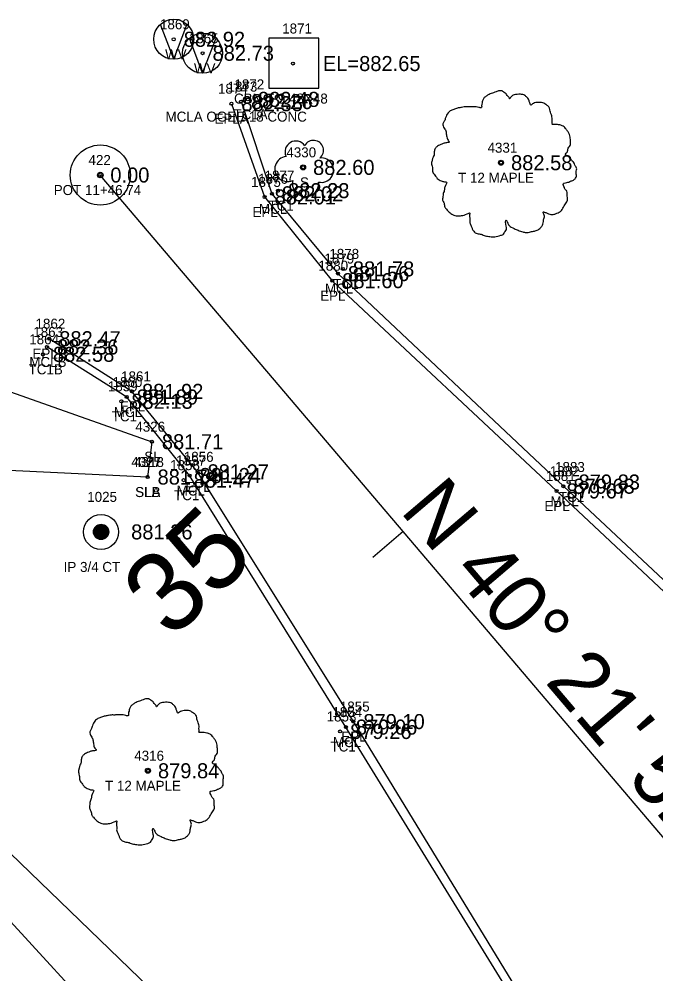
# Model space of a CAD drawing. Extents: x 1622501 to 1626664, y 1117816 to 1121579.
# Drawn here: x 1625349.1 to 1625412.8, y 1120671 to 1120766.3 of the extents above; entities that cross this region are included whole.
import ezdxf

# ---------------------------------------------------------------- set-up
doc = ezdxf.new("R2010")
doc.units = 0
for name, color, linetype in [('RD_EX_Bldg', 7, 'Continuous'), ('RD_EX_Conc', 7, 'Continuous'), ('RD_EX_Conc_txCode', 7, 'Continuous'), ('RD_EX_DR_Inlet', 7, 'Continuous'), ('RD_EX_DR_Inlet_txCode', 7, 'Continuous'), ('RD_EX_DV_Prop_txCode', 7, 'Continuous'), ('RD_EX_DV_PropPin', 7, 'Continuous'), ('RD_EX_Road', 7, 'Continuous'), ('RD_EX_Road_txCode', 7, 'Continuous'), ('RD_EX_TX_Conc_ELEV', 7, 'Continuous'), ('RD_EX_TX_DR_Inlet_ELEV', 7, 'Continuous'), ('RD_EX_TX_DV_Prop_ELEV', 7, 'Continuous'), ('RD_EX_TX_Road_ELEV', 7, 'Continuous'), ('RD_EX_TX_UT_ELEV', 7, 'Continuous'), ('RD_EX_TX_VEG_ELEV', 7, 'Continuous'), ('RD_EX_UT', 7, 'Continuous'), ('RD_EX_UT_txCode', 7, 'Continuous'), ('RD_EX_VEG', 7, 'Continuous'), ('RD_EX_VEG_txCode', 7, 'Continuous'), ('RD_HC_Cl', 7, 'Continuous'), ('RD_HC_Data', 7, 'Continuous'), ('RD_HC_Data_Tic', 7, 'Continuous'), ('RD_HC_Survey_ELEV', 7, 'Continuous'), ('RD_HC_TX_Sta50', 7, 'Continuous'), ('RD_HC_txCode', 7, 'Continuous'), ('RD_SMD_Locator', 7, 'Continuous')]:
    doc.layers.add(name, color=color, linetype=linetype)

msp = doc.modelspace()

# ---------------------------------------------------------------- linework, layer by layer
at = {"layer": 'RD_EX_Bldg'}
msp.add_lwpolyline([(1625324.146, 1120631.464), (1625359.464, 1120663.962), (1625332.745, 1120693.129), (1625297.427, 1120660.63), (1625324.146, 1120631.464)], dxfattribs=at)
at = {"layer": 'RD_EX_Conc'}
for points in [[(1625371.324, 1120758.09), (1625374.405, 1120748.878), (1625381, 1120740.913), (1625403.527, 1120719.673), (1625432.461, 1120692.614), (1625438.681, 1120687.207)], [(1625399.274, 1120667.189), (1625381.796, 1120695.608), (1625366.181, 1120720.74), (1625359.897, 1120728.578), (1625351.935, 1120733.581)]]:
    msp.add_lwpolyline(points, dxfattribs=at)
at = {"layer": 'RD_EX_DR_Inlet'}
msp.add_line((1625379.091, 1120759.438), (1625379.091, 1120764.438), dxfattribs=at)
msp.add_lwpolyline([(1625379.091, 1120759.438), (1625379.091, 1120764.438), (1625374.091, 1120764.438), (1625374.091, 1120759.438)], close=True, dxfattribs=at)
at = {"layer": 'RD_EX_DV_PropPin'}
for p, q in [((1625356.608, 1120714.912), (1625356.608, 1120715.304)), ((1625356.643, 1120714.81), (1625356.643, 1120715.406)), ((1625356.678, 1120714.739), (1625356.678, 1120715.478)), ((1625356.713, 1120714.682), (1625356.713, 1120715.535)), ((1625356.748, 1120714.634), (1625356.748, 1120715.582)), ((1625356.783, 1120714.593), (1625356.783, 1120715.623)), ((1625356.818, 1120714.557), (1625356.818, 1120715.659)), ((1625356.853, 1120714.526), (1625356.853, 1120715.69)), ((1625356.888, 1120714.498), (1625356.888, 1120715.718)), ((1625356.923, 1120714.474), (1625356.923, 1120715.743)), ((1625356.958, 1120714.452), (1625356.958, 1120715.764)), ((1625356.993, 1120714.432), (1625356.993, 1120715.784)), ((1625357.028, 1120714.415), (1625357.028, 1120715.801)), ((1625357.063, 1120714.401), (1625357.063, 1120715.816)), ((1625357.098, 1120714.388), (1625357.098, 1120715.829)), ((1625357.133, 1120714.377), (1625357.133, 1120715.84)), ((1625357.168, 1120714.367), (1625357.168, 1120715.849)), ((1625357.203, 1120714.36), (1625357.203, 1120715.856)), ((1625357.238, 1120714.354), (1625357.238, 1120715.862)), ((1625357.273, 1120714.35), (1625357.273, 1120715.866)), ((1625357.308, 1120714.348), (1625357.308, 1120715.868)), ((1625357.343, 1120714.347), (1625357.343, 1120715.869)), ((1625357.378, 1120714.348), (1625357.378, 1120715.868)), ((1625357.413, 1120714.35), (1625357.413, 1120715.866)), ((1625357.448, 1120714.354), (1625357.448, 1120715.862)), ((1625357.483, 1120714.36), (1625357.483, 1120715.856)), ((1625357.518, 1120714.367), (1625357.518, 1120715.849)), ((1625357.553, 1120714.377), (1625357.553, 1120715.84)), ((1625357.588, 1120714.388), (1625357.588, 1120715.829)), ((1625357.623, 1120714.401), (1625357.623, 1120715.816)), ((1625357.658, 1120714.415), (1625357.658, 1120715.801)), ((1625357.693, 1120714.432), (1625357.693, 1120715.784)), ((1625357.728, 1120714.452), (1625357.728, 1120715.764)), ((1625357.763, 1120714.474), (1625357.763, 1120715.743)), ((1625357.798, 1120714.498), (1625357.798, 1120715.718)), ((1625357.833, 1120714.526), (1625357.833, 1120715.69)), ((1625357.868, 1120714.557), (1625357.868, 1120715.659)), ((1625357.904, 1120714.593), (1625357.904, 1120715.623)), ((1625357.939, 1120714.634), (1625357.939, 1120715.582)), ((1625357.974, 1120714.682), (1625357.974, 1120715.535)), ((1625358.009, 1120714.739), (1625358.009, 1120715.478)), ((1625358.044, 1120714.81), (1625358.044, 1120715.406)), ((1625358.079, 1120714.912), (1625358.079, 1120715.304))]:
    msp.add_line(p, q, dxfattribs=at)
for radius in [1.75, 0.761]:
    msp.add_circle((1625357.343, 1120715.108), radius, dxfattribs=at)
at = {"layer": 'RD_EX_Road'}
for points in [[(1625370.364, 1120757.883), (1625373.672, 1120748.564), (1625380.435, 1120740.201), (1625402.846, 1120719.199), (1625431.886, 1120691.989), (1625438.078, 1120686.6), (1625445.87, 1120680.321), (1625455.5, 1120677.046), (1625462.434, 1120676.301), (1625468.216, 1120676.722), (1625470.162, 1120677.112), (1625477.587, 1120679.763), (1625479.605, 1120680.725), (1625482.392, 1120682.638), (1625486.867, 1120686.354)], [(1625193.609, 1120405.268), (1625230.886, 1120440.454), (1625264.542, 1120472.475), (1625302.319, 1120508.619), (1625336.712, 1120541.707), (1625372.736, 1120576.316), (1625405.889, 1120608.621), (1625410.004, 1120614.055), (1625413.225, 1120619.884), (1625415.316, 1120626.889), (1625415.744, 1120636.202), (1625413.752, 1120644.595), (1625411.823, 1120648.585), (1625399.983, 1120667.632), (1625382.545, 1120696.163), (1625366.978, 1120721.108), (1625360.429, 1120729.145), (1625352.16, 1120734.407)]]:
    msp.add_lwpolyline(points, dxfattribs=at)
at = {"layer": 'RD_EX_UT'}
for p, q in [((1625364.595, 1120762.324), (1625363.291, 1120765.806)), ((1625364.595, 1120762.324), (1625365.917, 1120765.769)), ((1625367.476, 1120760.927), (1625366.172, 1120764.41)), ((1625367.476, 1120760.927), (1625368.798, 1120764.373))]:
    msp.add_line(p, q, dxfattribs=at)
for centre in [(1625364.595, 1120764.316), (1625367.476, 1120762.92)]:
    msp.add_circle(centre, 2, dxfattribs=at)
at = {"layer": 'RD_EX_VEG'}
for points in [[(1625361.983, 1120720.589), (1625323.865, 1120722.423), (1625334.599, 1120733.918), (1625362.415, 1120724.119), (1625361.983, 1120720.589)], [(1625324.296, 1120690.104), (1625333.335, 1120697.407), (1625365.129, 1120666.703), (1625351.745, 1120650.415)]]:
    msp.add_lwpolyline(points, dxfattribs=at)
for centre, radius in [((1625397.3, 1120751.985), 0.25), ((1625377.522, 1120751.52), 0.25), ((1625397.287, 1120751.966), 0.0001), ((1625362.023, 1120691.25), 0.25), ((1625362.01, 1120691.231), 0.0001)]:
    msp.add_circle(centre, radius, dxfattribs=at)
for centre, radius, start, end in [((1625376.801, 1120753.067), 1.084, 34.97629, 204.75602), ((1625378.567, 1120753.222), 0.995, 308.76261, 152.04674), ((1625375.958, 1120751.365), 1.257, 96.45179, 294.73401), ((1625379.362, 1120751.241), 1.218, 256.56668, 98.10463), ((1625377.768, 1120749.924), 1.318, 166.88266, 5.75893)]:
    msp.add_arc(centre, radius, start, end, dxfattribs=at)
for points in [[(1625397.431, 1120759.152), (1625397.132, 1120759.177), (1625396.807, 1120759.077), (1625396.557, 1120758.977), (1625396.332, 1120758.902), (1625396.107, 1120758.802), (1625395.807, 1120758.627), (1625395.582, 1120758.427), (1625395.457, 1120758.177), (1625395.407, 1120757.953), (1625395.357, 1120757.678), (1625395.357, 1120757.503), (1625395.232, 1120757.478), (1625395.082, 1120757.503), (1625394.833, 1120757.578), (1625394.583, 1120757.578), (1625394.333, 1120757.578), (1625393.983, 1120757.553), (1625393.633, 1120757.553), (1625393.358, 1120757.503), (1625393.033, 1120757.453), (1625392.659, 1120757.328), (1625392.309, 1120757.203), (1625392.009, 1120756.953), (1625391.759, 1120756.478), (1625391.634, 1120756.128), (1625391.484, 1120755.878), (1625391.634, 1120755.429), (1625391.809, 1120755.079), (1625391.834, 1120754.879), (1625391.909, 1120754.454), (1625392.009, 1120754.229), (1625392.134, 1120754.029), (1625392.059, 1120754.004), (1625391.684, 1120753.954), (1625391.384, 1120753.854), (1625390.959, 1120753.629), (1625390.734, 1120753.405), (1625390.634, 1120753.08), (1625390.609, 1120752.73), (1625390.51, 1120752.53), (1625390.435, 1120752.255), (1625390.41, 1120752.18), (1625390.36, 1120751.855), (1625390.46, 1120751.405), (1625390.485, 1120751.056), (1625390.609, 1120750.831), (1625390.759, 1120750.656), (1625390.934, 1120750.406), (1625391.334, 1120750.181), (1625391.659, 1120750.081), (1625391.859, 1120750.056), (1625391.684, 1120749.556), (1625391.634, 1120749.206), (1625391.509, 1120748.807), (1625391.509, 1120748.732), (1625391.459, 1120748.257), (1625391.609, 1120747.932), (1625391.684, 1120747.557), (1625391.859, 1120747.332), (1625392.134, 1120747.032), (1625392.459, 1120746.807), (1625392.958, 1120746.682), (1625393.358, 1120746.707), (1625393.933, 1120746.882), (1625394.183, 1120746.957), (1625394.158, 1120746.782), (1625394.183, 1120746.408), (1625394.183, 1120745.983), (1625394.333, 1120745.658), (1625394.433, 1120745.383), (1625394.583, 1120745.133), (1625394.908, 1120744.908), (1625395.307, 1120744.833), (1625395.732, 1120744.683), (1625396.182, 1120744.608), (1625396.682, 1120744.583), (1625397.282, 1120744.733), (1625397.556, 1120744.858), (1625397.656, 1120745.033), (1625397.856, 1120745.408), (1625397.806, 1120745.633), (1625397.831, 1120746.233), (1625397.931, 1120746.058), (1625398.106, 1120745.708), (1625398.606, 1120745.408), (1625399.006, 1120745.233), (1625399.481, 1120745.083), (1625399.78, 1120745.008), (1625400.255, 1120745.083), (1625400.63, 1120745.158), (1625401.005, 1120745.283), (1625401.305, 1120745.558), (1625401.48, 1120745.833), (1625401.53, 1120746.108), (1625401.605, 1120746.483), (1625401.655, 1120746.657)], [(1625401.655, 1120746.657), (1625401.58, 1120746.832), (1625401.53, 1120747.082), (1625401.605, 1120747.057), (1625401.78, 1120747.007), (1625402.054, 1120746.882), (1625402.279, 1120746.807), (1625402.604, 1120746.832), (1625402.879, 1120746.932), (1625403.329, 1120747.207), (1625403.604, 1120747.682), (1625403.879, 1120748.082), (1625403.954, 1120748.407), (1625403.904, 1120748.632), (1625403.879, 1120749.131), (1625403.679, 1120749.381), (1625403.629, 1120749.506), (1625403.529, 1120749.906), (1625403.604, 1120749.956), (1625403.879, 1120750.006), (1625404.253, 1120750.131), (1625404.528, 1120750.256), (1625404.753, 1120750.431), (1625404.828, 1120750.656), (1625404.803, 1120751.056), (1625404.853, 1120751.455), (1625404.778, 1120751.605), (1625404.678, 1120751.755), (1625404.603, 1120751.955), (1625404.453, 1120752.105), (1625404.353, 1120752.255), (1625404.253, 1120752.355), (1625404.129, 1120752.505), (1625403.954, 1120752.63), (1625403.804, 1120752.68), (1625403.754, 1120752.83), (1625403.904, 1120753.03), (1625403.954, 1120753.13), (1625403.979, 1120753.355), (1625404.204, 1120753.704), (1625404.253, 1120754.104), (1625404.204, 1120754.529), (1625404.154, 1120754.804), (1625404.004, 1120755.079), (1625403.804, 1120755.329), (1625403.679, 1120755.504), (1625403.504, 1120755.629), (1625403.179, 1120755.754), (1625402.929, 1120755.803), (1625402.579, 1120755.803), (1625402.379, 1120755.853), (1625402.404, 1120755.903), (1625402.404, 1120756.053), (1625402.404, 1120756.328), (1625402.329, 1120756.778), (1625402.179, 1120757.278), (1625402.179, 1120757.303), (1625402.079, 1120757.553), (1625401.855, 1120757.753), (1625401.68, 1120757.853), (1625401.48, 1120757.978), (1625401.23, 1120758.003), (1625400.93, 1120758.003), (1625400.655, 1120757.953), (1625400.455, 1120757.853), (1625400.28, 1120757.728), (1625400.205, 1120757.878), (1625400.105, 1120758.177), (1625400.055, 1120758.327), (1625399.905, 1120758.502), (1625399.681, 1120758.702), (1625399.231, 1120758.827), (1625398.606, 1120758.752), (1625398.306, 1120758.552), (1625398.156, 1120758.377), (1625398.106, 1120758.502), (1625397.906, 1120758.702), (1625397.806, 1120758.877), (1625397.631, 1120759.002), (1625397.481, 1120759.102), (1625397.381, 1120759.152)], [(1625362.155, 1120698.418), (1625361.855, 1120698.443), (1625361.53, 1120698.343), (1625361.28, 1120698.243), (1625361.055, 1120698.168), (1625360.83, 1120698.068), (1625360.531, 1120697.893), (1625360.306, 1120697.693), (1625360.181, 1120697.443), (1625360.131, 1120697.218), (1625360.081, 1120696.943), (1625360.081, 1120696.768), (1625359.956, 1120696.743), (1625359.806, 1120696.768), (1625359.556, 1120696.843), (1625359.306, 1120696.843), (1625359.056, 1120696.843), (1625358.706, 1120696.818), (1625358.356, 1120696.818), (1625358.082, 1120696.768), (1625357.757, 1120696.718), (1625357.382, 1120696.593), (1625357.032, 1120696.468), (1625356.732, 1120696.218), (1625356.482, 1120695.744), (1625356.357, 1120695.394), (1625356.207, 1120695.144), (1625356.357, 1120694.694), (1625356.532, 1120694.344), (1625356.557, 1120694.144), (1625356.632, 1120693.72), (1625356.732, 1120693.495), (1625356.857, 1120693.295), (1625356.782, 1120693.27), (1625356.407, 1120693.22), (1625356.107, 1120693.12), (1625355.683, 1120692.895), (1625355.458, 1120692.67), (1625355.358, 1120692.345), (1625355.333, 1120691.995), (1625355.233, 1120691.795), (1625355.158, 1120691.521), (1625355.133, 1120691.446), (1625355.083, 1120691.121), (1625355.183, 1120690.671), (1625355.208, 1120690.321), (1625355.333, 1120690.096), (1625355.483, 1120689.921), (1625355.658, 1120689.671), (1625356.057, 1120689.446), (1625356.382, 1120689.346), (1625356.582, 1120689.322), (1625356.407, 1120688.822), (1625356.357, 1120688.472), (1625356.232, 1120688.072), (1625356.232, 1120687.997), (1625356.182, 1120687.522), (1625356.332, 1120687.197), (1625356.407, 1120686.823), (1625356.582, 1120686.598), (1625356.857, 1120686.298), (1625357.182, 1120686.073), (1625357.682, 1120685.948), (1625358.082, 1120685.973), (1625358.656, 1120686.148), (1625358.906, 1120686.223), (1625358.881, 1120686.048), (1625358.906, 1120685.673), (1625358.906, 1120685.248), (1625359.056, 1120684.923), (1625359.156, 1120684.649), (1625359.306, 1120684.399), (1625359.631, 1120684.174), (1625360.031, 1120684.099), (1625360.456, 1120683.949), (1625360.905, 1120683.874), (1625361.405, 1120683.849), (1625362.005, 1120683.999), (1625362.28, 1120684.124), (1625362.38, 1120684.299), (1625362.58, 1120684.674), (1625362.53, 1120684.898), (1625362.555, 1120685.498), (1625362.655, 1120685.323), (1625362.83, 1120684.973), (1625363.329, 1120684.674), (1625363.729, 1120684.499), (1625364.204, 1120684.349), (1625364.504, 1120684.274), (1625364.979, 1120684.349), (1625365.353, 1120684.424), (1625365.728, 1120684.549), (1625366.028, 1120684.823), (1625366.203, 1120685.098), (1625366.253, 1120685.373), (1625366.328, 1120685.748), (1625366.378, 1120685.923)], [(1625366.378, 1120685.923), (1625366.303, 1120686.098), (1625366.253, 1120686.348), (1625366.328, 1120686.323), (1625366.503, 1120686.273), (1625366.778, 1120686.148), (1625367.003, 1120686.073), (1625367.328, 1120686.098), (1625367.602, 1120686.198), (1625368.052, 1120686.473), (1625368.327, 1120686.948), (1625368.602, 1120687.347), (1625368.677, 1120687.672), (1625368.627, 1120687.897), (1625368.602, 1120688.397), (1625368.402, 1120688.647), (1625368.352, 1120688.772), (1625368.252, 1120689.172), (1625368.327, 1120689.222), (1625368.602, 1120689.272), (1625368.977, 1120689.396), (1625369.252, 1120689.521), (1625369.477, 1120689.696), (1625369.552, 1120689.921), (1625369.527, 1120690.321), (1625369.577, 1120690.721), (1625369.502, 1120690.871), (1625369.402, 1120691.021), (1625369.327, 1120691.221), (1625369.177, 1120691.371), (1625369.077, 1120691.521), (1625368.977, 1120691.62), (1625368.852, 1120691.77), (1625368.677, 1120691.895), (1625368.527, 1120691.945), (1625368.477, 1120692.095), (1625368.627, 1120692.295), (1625368.677, 1120692.395), (1625368.702, 1120692.62), (1625368.927, 1120692.97), (1625368.977, 1120693.37), (1625368.927, 1120693.795), (1625368.877, 1120694.069), (1625368.727, 1120694.344), (1625368.527, 1120694.594), (1625368.402, 1120694.769), (1625368.227, 1120694.894), (1625367.902, 1120695.019), (1625367.652, 1120695.069), (1625367.303, 1120695.069), (1625367.103, 1120695.119), (1625367.128, 1120695.169), (1625367.128, 1120695.319), (1625367.128, 1120695.594), (1625367.053, 1120696.044), (1625366.903, 1120696.543), (1625366.903, 1120696.568), (1625366.803, 1120696.818), (1625366.578, 1120697.018), (1625366.403, 1120697.118), (1625366.203, 1120697.243), (1625365.953, 1120697.268), (1625365.653, 1120697.268), (1625365.378, 1120697.218), (1625365.178, 1120697.118), (1625365.004, 1120696.993), (1625364.929, 1120697.143), (1625364.829, 1120697.443), (1625364.779, 1120697.593), (1625364.629, 1120697.768), (1625364.404, 1120697.968), (1625363.954, 1120698.093), (1625363.329, 1120698.018), (1625363.029, 1120697.818), (1625362.879, 1120697.643), (1625362.83, 1120697.768), (1625362.63, 1120697.968), (1625362.53, 1120698.143), (1625362.355, 1120698.268), (1625362.205, 1120698.368), (1625362.105, 1120698.418)]]:
    msp.add_spline(points, degree=3, dxfattribs=at)
at = {"layer": 'RD_HC_Cl'}
msp.add_line((1625452.301, 1120638.946), (1625357.264, 1120750.756), dxfattribs=at)
at = {"layer": 'RD_HC_Data'}
for radius in [3, 0.282]:
    msp.add_circle((1625357.264, 1120750.756), radius, dxfattribs=at)
at = {"layer": 'RD_HC_Data_Tic'}
msp.add_line((1625387.537, 1120715.141), (1625384.489, 1120712.55), dxfattribs=at)
at = {"layer": 'RD_SMD_Locator'}
for centre in [(1625364.595, 1120764.316), (1625367.476, 1120762.92), (1625376.5, 1120761.892), (1625370.364, 1120757.883), (1625371.324, 1120758.09), (1625372.01, 1120758.312), (1625377.522, 1120751.52), (1625397.3, 1120751.985), (1625357.264, 1120750.756), (1625375.022, 1120749.196), (1625373.672, 1120748.564), (1625374.405, 1120748.878), (1625381, 1120740.913), (1625381.495, 1120741.379), (1625380.435, 1120740.201), (1625352.16, 1120734.407), (1625351.935, 1120733.581), (1625351.531, 1120732.848), (1625360.429, 1120729.145), (1625359.364, 1120728.153), (1625359.897, 1120728.578), (1625362.415, 1120724.119), (1625361.983, 1120720.589), (1625361.983, 1120720.589), (1625366.181, 1120720.74), (1625366.978, 1120721.108), (1625365.586, 1120720.276), (1625403.527, 1120719.673), (1625404.048, 1120720.091), (1625402.846, 1120719.199), (1625357.343, 1120715.108), (1625382.545, 1120696.163), (1625381.224, 1120695.172), (1625381.796, 1120695.608), (1625362.023, 1120691.25)]:
    msp.add_circle(centre, 0.15, dxfattribs=at)

# ---------------------------------------------------------------- texts
at = {"layer": 'RD_EX_Conc_txCode'}
for s, p in [('1873', (1625369.977, 1120759.09)), ('1872', (1625370.663, 1120759.312)), ('MCLA OGEE 18 CONC', (1625363.78, 1120756.09)), ('TC1A', (1625370.561, 1120756.312)), ('1877', (1625373.675, 1120750.196)), ('1876', (1625373.035, 1120749.878)), ('MCL', (1625373.113, 1120746.878)), ('TC1', (1625374.061, 1120747.196)), ('1879', (1625379.654, 1120741.913)), ('1878', (1625380.148, 1120742.379)), ('MCL', (1625379.709, 1120738.913)), ('TC1', (1625380.534, 1120739.379)), ('1863', (1625350.565, 1120734.581)), ('1864', (1625350.161, 1120733.848)), ('MCLB', (1625350.171, 1120731.581)), ('TC1B', (1625350.098, 1120730.848)), ('1860', (1625358.488, 1120729.578)), ('1859', (1625358.017, 1120729.153)), ('MCL', (1625358.606, 1120726.578)), ('TC1', (1625358.403, 1120726.153)), ('1857', (1625364.835, 1120721.74)), ('1858', (1625364.24, 1120721.276)), ('1882', (1625402.181, 1120720.673)), ('1883', (1625402.701, 1120721.091)), ('MCL', (1625364.89, 1120718.74)), ('TC1', (1625364.626, 1120718.276)), ('TC1', (1625403.087, 1120718.091)), ('MCL', (1625402.236, 1120717.673)), ('1853', (1625379.878, 1120696.172)), ('1854', (1625380.449, 1120696.608)), ('TC1', (1625380.263, 1120693.172)), ('MCL', (1625380.504, 1120693.608))]:
    msp.add_text(s, height=1, dxfattribs=at).set_placement(p)
at = {"layer": 'RD_EX_DR_Inlet_txCode'}
for s, p in [('1871', (1625375.437, 1120764.892)), ('CBN T 9 48X48', (1625370.626, 1120757.892))]:
    msp.add_text(s, height=1, dxfattribs=at).set_placement(p)
at = {"layer": 'RD_EX_DV_Prop_txCode'}
for s, p in [('1025', (1625355.957, 1120718.108)), ('IP 3/4 CT', (1625353.603, 1120711.108))]:
    msp.add_text(s, height=1, dxfattribs=at).set_placement(p)
at = {"layer": 'RD_EX_Road_txCode'}
for s, p in [('1874', (1625369.018, 1120758.883)), ('EPLA', (1625368.671, 1120755.883)), ('1875', (1625372.326, 1120749.564)), ('EPL', (1625372.467, 1120746.564)), ('1880', (1625379.049, 1120741.201)), ('EPL', (1625379.231, 1120738.201)), ('1862', (1625350.79, 1120735.407)), ('EPLB', (1625350.483, 1120732.407)), ('1861', (1625359.342, 1120730.145)), ('EPL', (1625359.224, 1120727.145)), ('1856', (1625365.607, 1120722.108)), ('1881', (1625401.783, 1120720.199)), ('EPL', (1625365.773, 1120719.108)), ('EPL', (1625401.641, 1120717.199)), ('1855', (1625381.199, 1120697.163)), ('EPL', (1625381.341, 1120694.163))]:
    msp.add_text(s, height=1, dxfattribs=at).set_placement(p)
at = {"layer": 'RD_EX_TX_Conc_ELEV'}
for s, p in [('882.26', (1625372.324, 1120757.34)), ('882.48', (1625373.01, 1120757.562)), ('882.02', (1625375.405, 1120748.128)), ('882.23', (1625376.022, 1120748.446)), ('881.56', (1625382, 1120740.163)), ('881.78', (1625382.495, 1120740.629)), ('882.36', (1625352.935, 1120732.831)), ('882.58', (1625352.531, 1120732.098)), ('881.89', (1625360.897, 1120727.828)), ('882.13', (1625360.364, 1120727.403)), ('881.47', (1625366.586, 1120719.526)), ('881.24', (1625367.181, 1120719.99)), ('879.83', (1625405.048, 1120719.341)), ('879.63', (1625404.527, 1120718.923)), ('879.26', (1625382.224, 1120694.422)), ('879.06', (1625382.796, 1120694.858))]:
    msp.add_text(s, height=1.5, dxfattribs=at).set_placement(p)
at = {"layer": 'RD_EX_TX_DR_Inlet_ELEV'}
msp.add_text('EL=882.65', height=1.5, dxfattribs=at).set_placement((1625379.5, 1120761.142))
at = {"layer": 'RD_EX_TX_DV_Prop_ELEV'}
msp.add_text('881.26', height=1.5, dxfattribs=at).set_placement((1625360.343, 1120714.358))
at = {"layer": 'RD_EX_TX_Road_ELEV'}
for s, p in [('882.35', (1625371.364, 1120757.133)), ('882.01', (1625374.672, 1120747.814)), ('881.60', (1625381.435, 1120739.451)), ('882.47', (1625353.16, 1120733.657)), ('881.92', (1625361.429, 1120728.395)), ('881.27', (1625367.978, 1120720.358)), ('879.67', (1625403.846, 1120718.449)), ('879.10', (1625383.545, 1120695.413))]:
    msp.add_text(s, height=1.5, dxfattribs=at).set_placement(p)
at = {"layer": 'RD_EX_TX_UT_ELEV'}
for s, p in [('882.92', (1625365.595, 1120763.566)), ('882.73', (1625368.476, 1120762.17))]:
    msp.add_text(s, height=1.5, dxfattribs=at).set_placement(p)
at = {"layer": 'RD_EX_TX_VEG_ELEV'}
for s, p in [('882.60', (1625378.522, 1120750.77)), ('882.58', (1625398.3, 1120751.235)), ('881.71', (1625363.415, 1120723.369)), ('881.74', (1625362.983, 1120719.839)), ('881.74', (1625362.983, 1120719.839)), ('879.84', (1625363.023, 1120690.5))]:
    msp.add_text(s, height=1.5, dxfattribs=at).set_placement(p)
at = {"layer": 'RD_EX_UT_txCode'}
for s, p in [('1869', (1625363.225, 1120765.316)), ('1865', (1625366.106, 1120763.92)), ('WV', (1625363.736, 1120762.316)), ('WV', (1625366.618, 1120760.92))]:
    msp.add_text(s, height=1, dxfattribs=at).set_placement(p)
at = {"layer": 'RD_EX_VEG_txCode'}
for s, p in [('4330', (1625375.853, 1120752.52)), ('4331', (1625395.953, 1120752.985)), ('S', (1625377.215, 1120749.52)), ('T 12 MAPLE', (1625393.012, 1120749.985)), ('4326', (1625360.762, 1120725.119)), ('4327', (1625360.353, 1120721.589)), ('4318', (1625360.637, 1120721.589)), ('SL', (1625361.659, 1120722.119)), ('SLA', (1625360.739, 1120718.589)), ('SLB', (1625360.755, 1120718.589)), ('4316', (1625360.653, 1120692.25)), ('T 12 MAPLE', (1625357.735, 1120689.25))]:
    msp.add_text(s, height=1, dxfattribs=at).set_placement(p)
at = {"layer": 'RD_HC_Data'}
msp.add_text('N 40%%d 21\' 52" W', height=6, rotation=310.36437, dxfattribs=at).set_placement((1625387.11, 1120717.187))
at = {"layer": 'RD_HC_Survey_ELEV'}
msp.add_text('0.00', height=1.5, dxfattribs=at).set_placement((1625358.264, 1120750.006))
at = {"layer": 'RD_HC_TX_Sta50'}
msp.add_text('35', height=8, rotation=43.78375, dxfattribs=at).set_placement((1625364.35, 1120704.245))
at = {"layer": 'RD_HC_txCode'}
for s, p in [('422', (1625356.083, 1120751.756)), ('POT 11+46.74', (1625352.61, 1120748.756))]:
    msp.add_text(s, height=1, dxfattribs=at).set_placement(p)

doc.saveas('drawing.dxf')
